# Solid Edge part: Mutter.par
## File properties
Sűrűség: 0,000 kg/m^3
Pontosság: 0,990
Author: bmolnar
Last saved by: bmolnar
Revision: 76
Username: bmolnar
Dokumentum tartalom típus: 0
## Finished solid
Body 1: solid body, 23 faces, 46 edges, 24 vertices.
  Faces by surface: cone 14, plane 8, cylinder 1
  Edges by curve: spline 24, circle 16, line 6
Bounding box of the edges (mm): 8.000 x 27.713 x 24.000, from (0, -13.8564, -12) to (8, 13.8564, 12).
Cylindrical faces by radius (mm): R7.188 x1
Conical faces (half-angle, radius in mm at the cone's reference point): 60 deg R7.5939 x2, 60 deg R12.9282 x12
Planar faces by outward normal: +x 1, +z 1, -x 1, -z 1, oblique 4
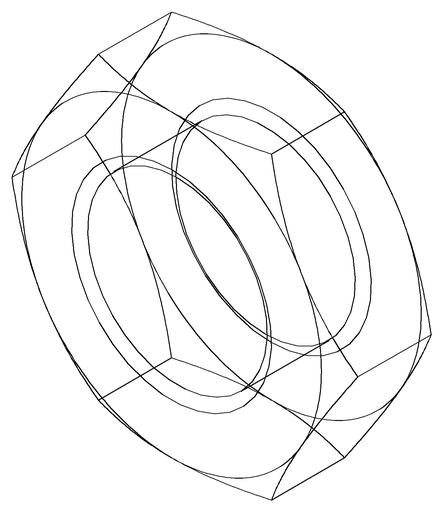
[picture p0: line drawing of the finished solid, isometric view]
